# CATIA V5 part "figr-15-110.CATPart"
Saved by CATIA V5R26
Part number: Part1
Bounding box of the stored display mesh (mm): x 0.737 to 206.429, y 0 to 112.04, z -1 to 2
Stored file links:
  D:\_Deepak\CATIA\CATIA V5 2015 Parts Files\Part files\Partfiles\c15_catia_v5_6r2015_prt\figr-15-110.CATPart
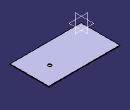
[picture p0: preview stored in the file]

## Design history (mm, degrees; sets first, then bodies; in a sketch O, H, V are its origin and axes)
SheetMetalParameters1: Thickness 2, BendRadius 4, KFactor 0.400515 {= log(min(100,max(20*SheetMetalParameters1.BendRadius,SheetMetalParameters1.Thickness)/SheetMetalParameters1.Thickness))/log(100)/2}, ReliefRadialLength 1, ReliefAxialLength 2, MinimumBendRadius 0
Body1 (main body)
  Sketch1 on xy-plane, origin (0, 0, 0), H (1, 0, 0), V (0, 1, 0)
    line L1 (0.7372, 112.0403) -> (206.4285, 112.0403)
    line L2 (206.4285, 112.0403) -> (206.4285, 0)
    line L3 (206.4285, 0) -> (0.7372, 0)
    line L4 (0.7372, 0) -> (0.7372, 112.0403)
    horizontal: L1 H, L3 H
    vertical: L2 V, L4 V
  Wall1: Thickness 2, Profile Sketch1, OffsetValue 0
  Sketch2 on face of Wall1, origin (152.409, 60.7083, 2), H (1, 0, 0), V (0, 1, 0)
    point P1 (0, 0)
  d_Stamp1: Stamp_FilletActivity false, KFacteur 0.400515 {= SheetMetalParameters1.KFactor}, NewRoot_AttribNormalisation "No Standard", Stamp_FilletRadius 2, Stamp_IntersectFilletRadius 2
